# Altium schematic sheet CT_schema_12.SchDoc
size 386 x 278 mm
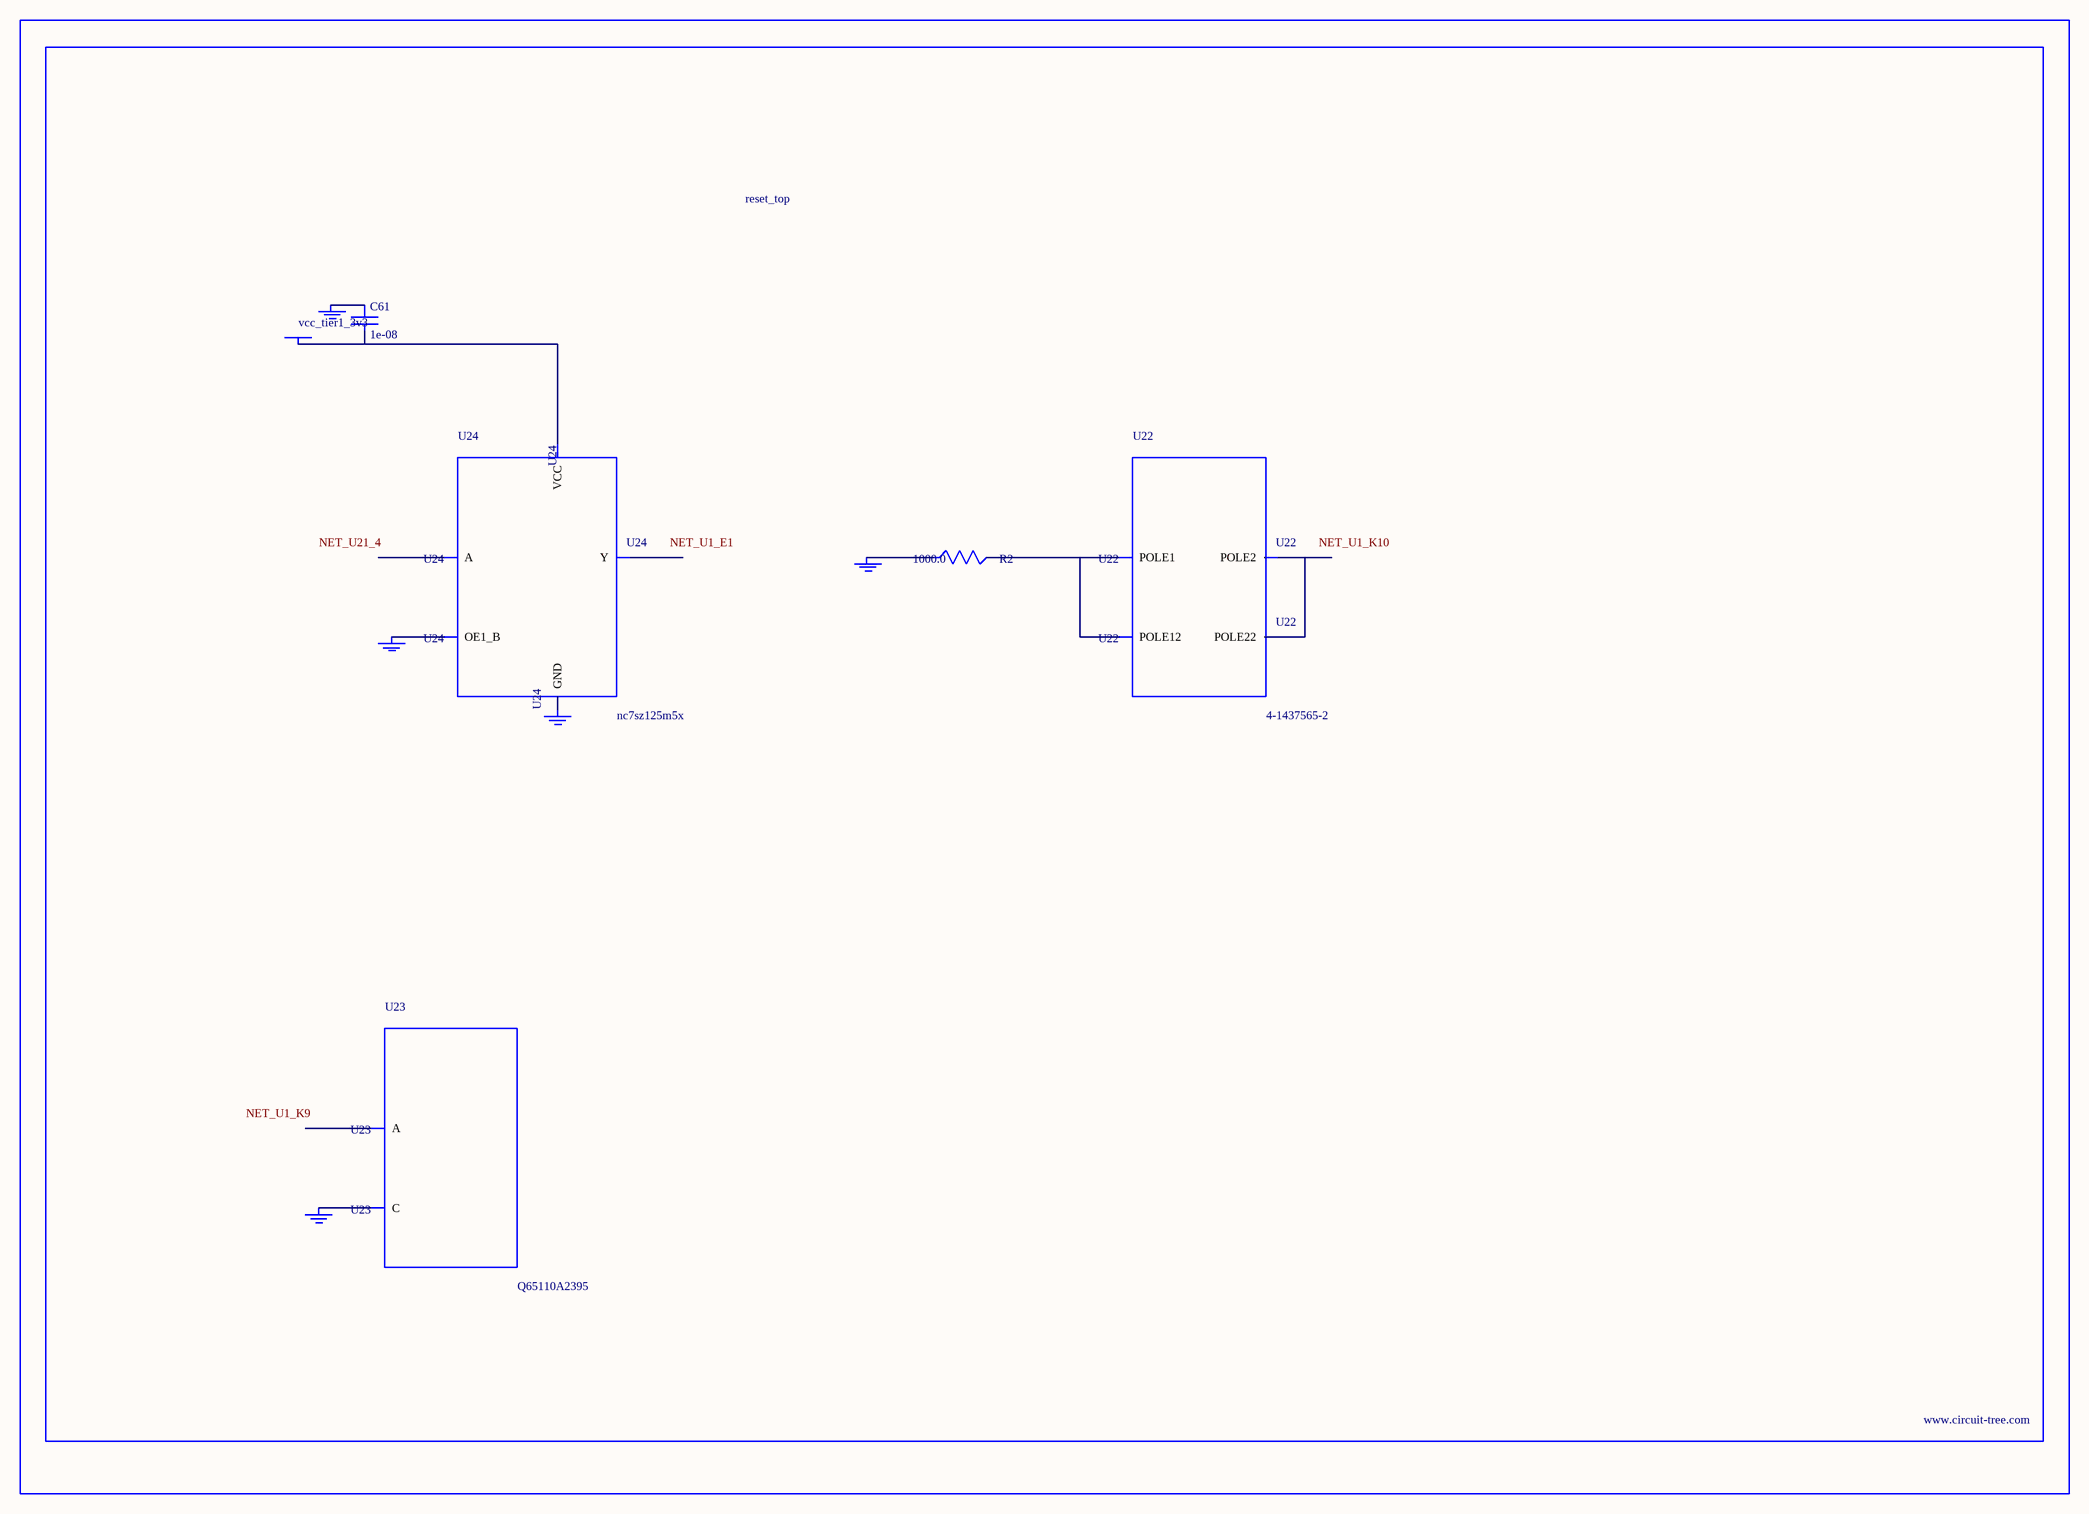
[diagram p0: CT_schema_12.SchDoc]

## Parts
BORDER11  (no value)
C61  1e-08  [C0402]
GND_INSTANCE_11_0  (no value)
GND_INSTANCE_11_1  (no value)
GND_INSTANCE_11_2  (no value)
GND_INSTANCE_11_3  (no value)
GND_INSTANCE_11_4  (no value)
POWER_INSTANCE_11_0  vcc_tier1_3v3
R2  1000.0  [R0603]
U22  4-1437565-2  [SW_4-1437565-2]
U23  Q65110A2395  [LGM67K-G1J2-24-Z]
U24  nc7sz125m5x  [NC7SZ125M5X]

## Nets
NetC61_1: C61.1 GND_INSTANCE_11_2.0(GND)
NetC61_2: C61.2 POWER_INSTANCE_11_0.0(PWR) U24.5(VCC)
NetGND_INSTANCE_11_0_0: GND_INSTANCE_11_0.0(GND) R2.1
NetGND_INSTANCE_11_1_0: GND_INSTANCE_11_1.0(GND) U23.C
NetGND_INSTANCE_11_3_0: GND_INSTANCE_11_3.0(GND) U24.1(OE1_B)
NetGND_INSTANCE_11_4_0: GND_INSTANCE_11_4.0(GND) U24.3(GND)
NetR2_2: R2.2 U22.1(POLE1) U22.2(POLE12)
NetU22_3: U22.3(POLE2) U22.4(POLE22)

Not connected (* = marked no-connect by the designer): U23 A; U24 2(A) 4(Y)

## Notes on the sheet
- Labels drawn without touching a wire or pin: NET_U1_E1, NET_U1_K9, NET_U1_K10, NET_U21_4

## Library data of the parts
BORDER11 = BORDER_PAGE11
C61 = C0402C103K3RAC
GND_INSTANCE_11_0-GND_INSTANCE_11_4 = GND
POWER_INSTANCE_11_0 = PWR
R2 = RC0603JR-071KL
